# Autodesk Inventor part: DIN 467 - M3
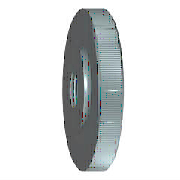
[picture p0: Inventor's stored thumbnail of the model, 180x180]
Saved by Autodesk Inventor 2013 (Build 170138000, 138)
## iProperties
IsCustomPart: 0
Created: 2012-02
Part Number: DIN 467 - M3
Material: Stahl, weich
Description: Rändelmutter
Document SubType Name: Modeling
Standard: DIN 467
Designer: rYan
Standards Organization: DIN
Language: de-DE
Size Designation: M3
Categories: <MemberInstance><Categories><Category DisplayName="Verbindungselemente" InternalName="e4da775c-781d-43d5-af7c-5136215cf5a6" Mnemonic="FSTN"><Category DisplayNam
Density: 1 g/cm^3
Author: rYan
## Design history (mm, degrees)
body "Solid1"
revolve "Körper" stored, may be unused: angle "d8" = 90 deg
sketch "Skizze2"
  geometry: L1 (0, 0)-(0, 6); L2 (-0.25, 5.995)-(0, 5.745); L3 (0.25, 5.995)-(0, 5.745); C1 r 3 at (0, 0) reference; A1 r 6 centre (0, 0) between (0, 6) and (-0.25, 5.995) reference; A2 r 6 centre (0, 0) between (0.25, 5.995) and (-0.25, 5.995); 1 further point
  constraints: 6 end point, 5 point on circle, 1 centre point, 1 coincident, 1 point on line, 1 symmetric about line, 1 vertical, 1 other
  dimensions: "d4" = 90 deg angle of L3 L2; "d5" = 0.25 distance from line of L1 L2.start (= 0.5 x T)
chamfer "Fase1" distance "d13" = 0.3 (= PHH); stored, may be unused: angle "d15" = 45 deg (= FAWI), second distance "d36" = 0.3 (= PHH)
chamfer "Fase2" distance "d23" = 0.3 (= PHH); stored, may be unused: angle "d24" = 45 deg (= FAWI), second distance "d37" = 0.3 (= PHH)
extrude "Nut1" cut sketch "Skizze2" taper "d6" = 0 deg; stored distance "d11" = 10
pattern_circular "Nuten1" dims angle "d9" = 360 deg
hole "Gewinde" sketch "Skizze2" diameter "d16" = 2.459; stored, may be unused: countersink angle "d20" = 82 deg, drill point angle "d22" = 118 deg; dims "d17" = 6, "d18" = 4, "d19" = 2, "d21" = 8
chamfer "Fase3" distance "d10" = 0.27063 (= -0.5 x GD1 + 0.5 x NND); stored, may be unused: angle "d12" = 30 deg, second distance "d38" = 0.27063 (= -0.5 x GD1 + 0.5 x NND)
workaxis "Work Axis1"
workplane "Work Plane1"
sketch "Skizze1"
  geometry: L1 (0, 0)-(-3, 0) reference; L2 (0, 0)-(0, 6) reference; L3 (0, 6)-(-2.5, 6); L4 (-2.5, 6)-(-2.5, 3.5); L5 (-3, 3)-(-3, 3); L6 (-3, 3)-(-3, 0); A1 r 0.5 centre (-3, 3.5) between (-3, 3) and (-2.5, 3.5)
  constraints: 12 end point, 5 perpendicular, 2 horizontal, 2 point on circle, 2 tangent, 1 centre point, 1 point on line, 1 vertical
  dimensions: "d0" = 0.5 radius of A1 (= RR); "d1" = 3 distance of L1.start L1.end (= KOH); "d2" = 12 diameter of L3 L1 (= KOD); "d3" = 6 diameter of L5.end L1 (= BDM)
other parameters: "FAWI" = 45 deg [user parameter; used in 2 equation terms], "T" = 0.5 [user parameter; used in 2 equation terms], "NND" = 3 [user parameter; used in 2 equation terms], "KOD" = 12 [user parameter; used in 2 equation terms], "KOH" = 3 [user parameter; used in 1 equation term], "KOH1" = 2.5 [user parameter], "BDM" = 6 [user parameter; used in 1 equation term], "PHH" = 0.3 [user parameter; used in 4 equation terms], "GD1" = 2.45873 (computed from THREADDIA, PTC, TOA) [user parameter; used in 2 equation terms], "d25" = 0, "d26" = 0, "RR" = 0.5 [user parameter; used in 1 equation term], "d27" = 0, "d39" = 0, "GUL" = 0.27063 (= 0.541266 x PTC) [user parameter], "THREADDIA" = 3 [user parameter; used in 1 equation term], "TOA" = 30 deg [user parameter; used in 1 equation term], "PTC" = 0.5 [user parameter; used in 4 equation terms], "GAL" = 0.27063 (= 0.541266 x PTC) [user parameter]
